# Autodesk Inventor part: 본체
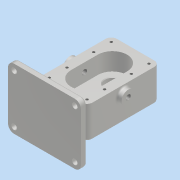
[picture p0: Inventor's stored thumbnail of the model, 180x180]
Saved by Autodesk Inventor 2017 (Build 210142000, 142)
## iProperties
Part Number: 본체
Material: 알루미늄 6061
Document SubType Name: Modeling
Designer: MRC
Density: 2.7 g/cm^3
Appearance: 알루미늄 - 평지
Mass: 1471.9 g
Surface Area: 819.891 cm^2
Volume: 545.148 cm^3
Author: MRC
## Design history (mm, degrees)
sketch "스케치1"
  geometry: L1 (-40, -60)-(40, -60); L2 (40, -60)-(40, 60); L3 (40, 60)-(-40, 60); L4 (-40, 60)-(-40, -60); L5 (-40, -60)-(40, 60); L6 (40, -60)-(-40, 60); 1 further point
  constraints: 12 end point, 2 midpoint, 2 parallel, 1 horizontal, 1 perpendicular
  dimensions: "d0" = 80 distance of L3.end L2.end; "d1" = 120 distance of L2.end L1.end
extrude "돌출1" new body sketch "스케치1" distance "d2" = 14; taper "d3" = 0 deg; dims "d6" = 39, "d7" = 0
sketch "스케치3"
  geometry: L1 (0, 22)-(0, -22); L2 (-24, 22)-(-24, -22); L3 (24, -22)-(24, 22); A1 r 24 centre (0, 22) between (24, 22) and (-24, 22); A2 r 24 centre (0, -22) between (-24, -22) and (24, -22); 4 further points
  constraints: 8 end point, 5 point on circle, 4 tangent, 2 centre point, 2 midpoint, 1 horizontal alignment, 1 parallel, 1 vertical, 1 vertical alignment
  dimensions: "d8" = 92 dimension on A2 A1; "d9" = 24 radius of A1
extrude "돌출2" cut sketch "스케치3" distance "d10" = 29; taper "d11" = 0 deg
sketch "스케치5"
  geometry: C1 r 19 at (0, 22); A1 r 24 centre (0, 22) between (24, 22) and (-24, 22) reference; 1 further point
  constraints: 1 centre point, 1 coincident
  dimensions: "d13" = 38 diameter of C1
extrude "돌출3" join sketch "스케치5" distance "d14" = 41; taper "d15" = 0 deg
sketch "스케치6"
  geometry: C1 r 19 at (0, 0) reference; C2 r 14 at (0, 0); 1 further point
  constraints: 1 centre point, 1 coincident
  dimensions: "d16" = 28 diameter of C2
extrude "돌출4" cut sketch "스케치6" distance "d17" = 7.3; taper "d18" = 0 deg
fillet "모깎기1" dims "d19" = 0.5
sketch "스케치7"
  geometry: C1 r 11 at (14, 60); 1 further point
  constraints: 1 centre point, 1 coincident
  dimensions: "d20" = 22 diameter of C1
extrude "돌출5" join sketch "스케치7" distance "d21" = 8; taper "d22" = 0 deg
hole "구멍1" diameter "d25" = 8.376; stored, may be unused: countersink angle "d29" = 90 deg, drill point angle "d31" = 118 deg; dims "d23" = 10, "d24" = 10, "d26" = 30, "d27" = 4, "d28" = 2, "d30" = 27.3
sketch "스케치8"
  geometry: A1 r 24 centre (0, 22) between (24, 22) and (-24, 22) reference; 1 further point
hole "구멍2" sketch "스케치8" at (0, 22) diameter "d33" = 17; stored, may be unused: countersink angle "d37" = 90 deg, drill point angle "d39" = 118 deg; dims "d34" = 20, "d35" = 25, "d36" = 15, "d38" = 27.3
sketch "스케치9"
  geometry: C1 r 12.5 at (0, -22); A1 r 24 centre (0, -22) between (-24, -22) and (24, -22) reference; 1 further point
  constraints: 1 centre point, 1 coincident
  dimensions: "d40" = 25 diameter of C1
extrude "돌출6" cut sketch "스케치9" distance "d41" = 15; taper "d42" = 0 deg
fillet "모깎기3" dims "d43" = 9
sketch "스케치10"
  geometry: A1 r 9 centre (-31, 51) between (-31, 60) and (-40, 51) reference; 2 further points
  constraints: 1 coincident
hole "구멍3" sketch "스케치10" at (-31, 51) diameter "d44" = 4.134; stored, may be unused: countersink angle "d48" = 90 deg, drill point angle "d50" = 118 deg; dims "d45" = 10, "d46" = 25, "d47" = 15, "d49" = 12
sketch "스케치11"
  geometry: C1 r 2.067 at (31, 51) reference; C2 r 2.067 at (-31, 51) reference; C3 r 2.067 at (31, -51) reference; A1 r 9 centre (-31, 51) between (-31, 60) and (-40, 51) reference; A2 r 24 centre (0, -22) between (-24, -22) and (24, -22) reference; A3 r 24 centre (0, 22) between (24, 22) and (-24, 22) reference; 5 further points
  constraints: 3 horizontal alignment, 3 vertical alignment
  dimensions: "d54" = 29 distance of C2.centre point (-31, 22); "d55" = 29 distance of C1.centre point (31, 22)
hole "구멍4" sketch "스케치11" at (-31, 22), (31, 22), (31, -22), (-31, -22) diameter "d56" = 4.134; stored, may be unused: countersink angle "d60" = 90 deg, drill point angle "d62" = 118 deg; dims "d57" = 10, "d58" = 25, "d59" = 15, "d61" = 12
node "작업 평면1"
sketch "스케치12"
  geometry: L1 (60, 44)-(-60, 44); L2 (-60, 44)-(-60, -56); L3 (-60, -56)-(60, -56); L4 (60, -56)-(60, 44); L5 (-19, -56)-(19, -56) reference; 2 further points
  constraints: 8 end point, 2 parallel, 1 collinear, 1 horizontal, 1 midpoint, 1 perpendicular, 1 vertical alignment
  dimensions: "d64" = 100 distance of L3.end L1.start; "d65" = 120 distance of L1.start L1.end
extrude "돌출7" join sketch "스케치12" distance "d66" = 10; taper "d67" = 0 deg
fillet "모깎기4" dims "d68" = 10
chamfer "모따기1" distance "d72" = 0.7; stored, may be unused: second distance "d73" = 2, angle "d74" = 30 deg
sketch "스케치14"
  geometry: L1 (-60, 2.453)-(-80, 14); L2 (-80, 14)-(-80, -39); L3 (-80, -39)-(-60, -27.453); L4 (-60, -27.453)-(-60, 2.453); L5 (-90, -56)-(-80, -56) reference; L6 (-80, -46)-(-80, 34) reference; L7 (-60, -39)-(-60, 14) reference; 1 further point
  constraints: 8 end point, 2 collinear, 1 equal length, 1 parallel, 1 vertical
  dimensions: "d81" = 17 distance from line of L2.end L5; "d82" = 60 deg angle of L2 L3; "d83" = 53 distance of L1.end L2.end
extrude "돌출10" join sketch "스케치14" stored distance "d84" = 48; taper "d85" = 0 deg
sketch "스케치15"
  geometry: C1 r 4.5 at (-50, -34); C2 r 4.5 at (-50, 46); C3 r 4.5 at (50, 46); C4 r 4.5 at (50, -34); A1 r 10 centre (-50, 46) between (-50, 56) and (-60, 46) reference; A2 r 10 centre (-50, -34) between (-60, -34) and (-50, -44) reference; A3 r 10 centre (50, -34) between (50, -44) and (60, -34) reference; A4 r 10 centre (50, 46) between (60, 46) and (50, 56) reference; 1 further point
  constraints: 4 centre point, 4 coincident
  dimensions: "d86" = 9 diameter of C1; "d87" = 9 diameter of C2; "d88" = 9 diameter of C3; "d89" = 9 diameter of C4
extrude "돌출11" cut sketch "스케치15" distance "d90" = 48; taper "d91" = 0 deg
sketch "스케치16"
  geometry: L1 (-60, 46)-(-60, -34) reference; L2 (-50, -44)-(50, -44) reference; 2 further points
  constraints: 1 other
  dimensions: "d102" = 60 distance from line of L1 point (0, -34); "d103" = 10 distance from line of L2 point (0, -34)
feature "엠보싱1" sketch "스케치16" dims "d0" = 80, "d1" = 120, "d92" = 0.5, "d93" = 0
chamfer "모따기2" distance "d94" = 1; stored, may be unused: second distance "d95" = 2, angle "d96" = 30 deg
fillet "모깎기5" dims "d97" = 3
fillet "모깎기6" dims "d98" = 3
fillet "모깎기7" dims "d99" = 3
fillet "모깎기8" dims "d100" = 3
node "솔리드1"
mirror "미러1"
pattern_linear "직사각형 패턴1" dims "d53" = 62
mirror "미러2"
